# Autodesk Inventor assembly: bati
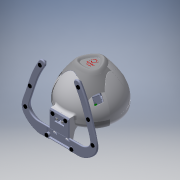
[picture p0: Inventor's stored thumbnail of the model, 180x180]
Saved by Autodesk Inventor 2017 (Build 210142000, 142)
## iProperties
Created: 2013-10
Part Number: bati
Material: Générique
Document SubType Name: Assembly
Designer: Bruno
Sending System: SolidWorks 2013
Last Author: christophe
Last Saved: 2014-02-15
Author: Bruno
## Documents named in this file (16)
- D:\Cours\1-Cours-2018-19\1Ssi\7- EDC-mvt\Haptique-2017\Reel-Inventor\bati.iam
- D:\Cours\1-Cours-2018-19\1Ssi\7- EDC-mvt\Haptique-2017\Reel-Inventor\MOTEUR.ipt
- D:\Cours\1-Cours-2018-19\1Ssi\7- EDC-mvt\Haptique-2017\Reel-Inventor\FIXATION MOTEUR.ipt
- D:\Cours\1-Cours-2018-19\1Ssi\7- EDC-mvt\Haptique-2017\Reel-Inventor\Vis à tôle tête cylindrique cruciforme H 2,9x13 - C.ipt
- D:\Cours\1-Cours-2018-19\1Ssi\7- EDC-mvt\Haptique-2017\Reel-Inventor\socle.ipt
- D:\Cours\1-Cours-2018-19\1Ssi\7- EDC-mvt\Haptique-2017\Reel-Inventor\vis CHC M4-30.ipt
- D:\Cours\1-Cours-2018-19\1Ssi\7- EDC-mvt\Haptique-2017\Reel-Inventor\Rondelle M4.ipt
- D:\Cours\1-Cours-2018-19\1Ssi\7- EDC-mvt\Haptique-2017\Reel-Inventor\CARTE HEXAGONALE.ipt
- D:\Cours\1-Cours-2018-19\1Ssi\7- EDC-mvt\Haptique-2017\Reel-Inventor\petite carte.ipt
- D:\Cours\1-Cours-2018-19\1Ssi\7- EDC-mvt\Haptique-2017\Reel-Inventor\Vis à tôle tête cylindrique cruciforme H 2,9x8 - C.ipt
- D:\Cours\1-Cours-2018-19\1Ssi\7- EDC-mvt\Haptique-2017\Reel-Inventor\plaque fixation.ipt
- D:\Cours\1-Cours-2018-19\1Ssi\7- EDC-mvt\Haptique-2017\Reel-Inventor\CARTER ARRIERE.ipt
- D:\Cours\1-Cours-2018-19\1Ssi\7- EDC-mvt\Haptique-2017\Reel-Inventor\carter transparant.iam
- D:\Cours\1-Cours-2018-19\1Ssi\7- EDC-mvt\Haptique-2017\Reel-Inventor\carter avant.iam
- D:\Cours\1-Cours-2018-19\1Ssi\7- EDC-mvt\Haptique-2017\Reel-Inventor\PLAQUE NOM.ipt
- D:\Cours\1-Cours-2018-19\1Ssi\7- EDC-mvt\Haptique-2017\Reel-Inventor\CACHE.ipt
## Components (51 placed, 15 different names)
1. MOTEUR:1
2. FIXATION MOTEUR:1
3. FIXATION MOTEUR:2
4. Vis à tôle tête cylindrique cruciforme H 2,9x13 - C:1
5. Vis à tôle tête cylindrique cruciforme H 2,9x13 - C:2
6. Vis à tôle tête cylindrique cruciforme H 2,9x13 - C:3
7. Vis à tôle tête cylindrique cruciforme H 2,9x13 - C:4
8. socle:1
9. vis CHC M4-30:1
10. vis CHC M4-30:2
11. Rondelle M4:1
12. Rondelle M4:2
13. CARTE HEXAGONALE:1
14. Vis à tôle tête cylindrique cruciforme H 2,9x13 - C:5
15. petite carte:1
16. Vis à tôle tête cylindrique cruciforme H 2,9x8 - C:1
17. Vis à tôle tête cylindrique cruciforme H 2,9x13 - C:7
18. Vis à tôle tête cylindrique cruciforme H 2,9x8 - C:2
19. Vis à tôle tête cylindrique cruciforme H 2,9x8 - C:3
20. petite carte:2
21. petite carte:3
22. Vis à tôle tête cylindrique cruciforme H 2,9x13 - C:8
23. Vis à tôle tête cylindrique cruciforme H 2,9x13 - C:9
24. Vis à tôle tête cylindrique cruciforme H 2,9x13 - C:10
25. Vis à tôle tête cylindrique cruciforme H 2,9x13 - C:11
26. Vis à tôle tête cylindrique cruciforme H 2,9x13 - C:12
27. Vis à tôle tête cylindrique cruciforme H 2,9x13 - C:13
28. Vis à tôle tête cylindrique cruciforme H 2,9x13 - C:14
29. Vis à tôle tête cylindrique cruciforme H 2,9x13 - C:15
30. MOTEUR:2
31. MOTEUR:3
32. FIXATION MOTEUR:3
33. FIXATION MOTEUR:4
34. Vis à tôle tête cylindrique cruciforme H 2,9x13 - C:16
35. Vis à tôle tête cylindrique cruciforme H 2,9x13 - C:17
36. plaque fixation:1
37. CARTER ARRIERE:1
38. carter transparant:5 [sub-assembly]
39. Vis à tôle tête cylindrique cruciforme H 2,9x13 - C:18
40. Vis à tôle tête cylindrique cruciforme H 2,9x13 - C:19
41. Vis à tôle tête cylindrique cruciforme H 2,9x13 - C:20
42. Vis à tôle tête cylindrique cruciforme H 2,9x13 - C:21
43. Vis à tôle tête cylindrique cruciforme H 2,9x13 - C:22
44. Vis à tôle tête cylindrique cruciforme H 2,9x13 - C:23
45. carter avant:1 [sub-assembly]
46. FIXATION MOTEUR:5
47. FIXATION MOTEUR:6
48. PLAQUE NOM:1
49. CACHE:1
50. CACHE:2
51. CACHE:3
